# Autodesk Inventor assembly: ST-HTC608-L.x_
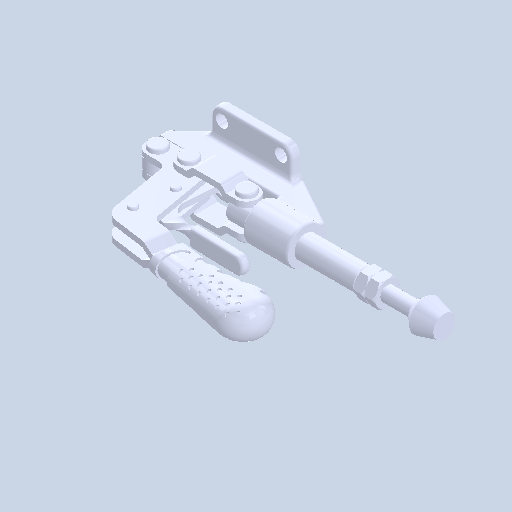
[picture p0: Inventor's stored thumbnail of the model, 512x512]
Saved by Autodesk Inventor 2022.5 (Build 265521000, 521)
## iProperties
Created: 2024-07
Part Number: ST-HTC608-L.x_
Document SubType Name: Assembly
Designer: ImaoCorp
Author: ImaoCorp
Sending System: SOLIDWORKS 2022-2022290
MC: AMD64
MC_MODEL: Intel64 Family 6 Model 60 Stepping 3, GenuineIntel
OS: Windows_NT
FRU: Parasolid Version 33.1, build 260,  4-25-2022
FORMAT: text
GUISE: transmit
KEY: FILEST-HTC608-L.x_t
DATE: Mon Jul 29 10:02:59 2024
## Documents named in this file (6)
- X:\14_SW2022-Inv2022\07_2024-10新製品(WHS)\OTC_データ\s\st-htc608-l\ST-HTC608-L.x_.iam
- X:\14_SW2022-Inv2022\07_2024-10新製品(WHS)\OTC_データ\s\st-htc608-l\ST-HTC680-L_01.ipt
- X:\14_SW2022-Inv2022\07_2024-10新製品(WHS)\OTC_データ\s\st-htc608-l\ST-HTC680-L_02.ipt
- X:\14_SW2022-Inv2022\07_2024-10新製品(WHS)\OTC_データ\s\st-htc608-l\ST-HTC680-L_03.ipt
- X:\14_SW2022-Inv2022\07_2024-10新製品(WHS)\OTC_データ\s\st-htc608-l\ST-HTC680-L_04.ipt
- X:\14_SW2022-Inv2022\07_2024-10新製品(WHS)\OTC_データ\s\st-htc608-l\ST-HTC680-L_05.ipt
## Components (5 placed, 5 different names)
1. ST-HTC680-L_01
2. ST-HTC680-L_02
3. ST-HTC680-L_03
4. ST-HTC680-L_04
5. ST-HTC680-L_05
